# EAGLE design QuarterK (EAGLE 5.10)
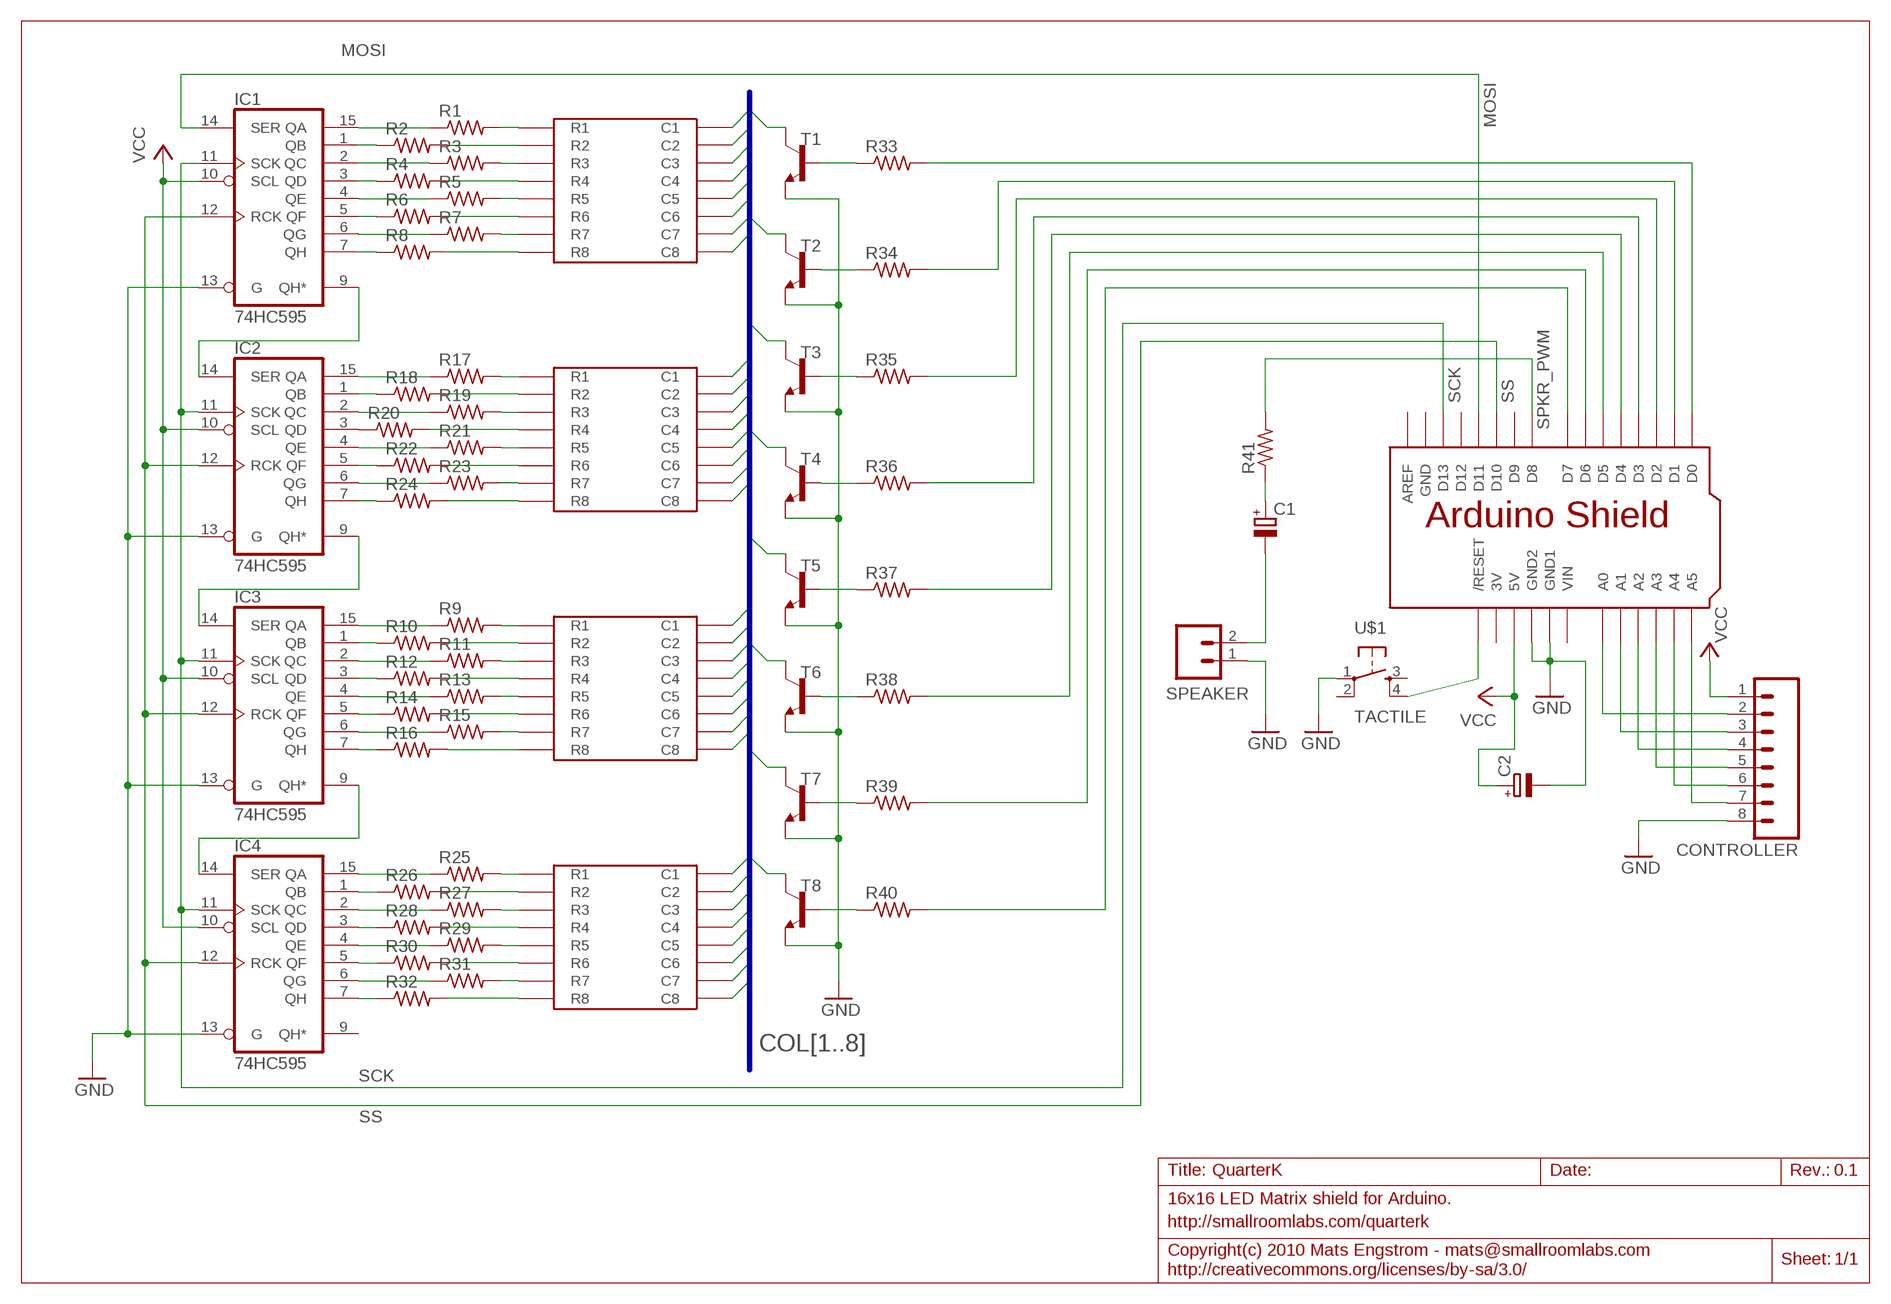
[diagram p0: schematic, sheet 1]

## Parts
C1  CPOL-EUE2.5-5  [E2,5-5]
C2  CPOL-EUE2.5-5  [E2,5-5]
CONTROLLER  M08  [1X08]
DISP1  LE-MM101STD  [LEDMATRIX-20MM-A]
DISP2  LE-MM101STD  [LEDMATRIX-20MM-A]
DISP3  LE-MM101STD  [LEDMATRIX-20MM-A]
DISP4  LE-MM101STD  [LEDMATRIX-20MM-A]
IC1  74HC595  74LS595N  [DIL16]
IC2  74HC595  74LS595N  [DIL16]
IC3  74HC595  74LS595N  [DIL16]
IC4  74HC595  74LS595N  [DIL16]
R1  R-US_0207/2V  [0207/2V]
R2  R-US_0207/2V  [0207/2V]
R3  R-US_0207/2V  [0207/2V]
R4  R-US_0207/2V  [0207/2V]
R5  R-US_0207/2V  [0207/2V]
R6  R-US_0207/2V  [0207/2V]
R7  R-US_0207/2V  [0207/2V]
R8  R-US_0207/2V  [0207/2V]
R9  R-US_0207/2V  [0207/2V]
R10  R-US_0207/2V  [0207/2V]
R11  R-US_0207/2V  [0207/2V]
R12  R-US_0207/2V  [0207/2V]
R13  R-US_0207/2V  [0207/2V]
R14  R-US_0207/2V  [0207/2V]
R15  R-US_0207/2V  [0207/2V]
R16  R-US_0207/2V  [0207/2V]
R17  R-US_0207/2V  [0207/2V]
R18  R-US_0207/2V  [0207/2V]
R19  R-US_0207/2V  [0207/2V]
R20  R-US_0207/2V  [0207/2V]
R21  R-US_0207/2V  [0207/2V]
R22  R-US_0207/2V  [0207/2V]
R23  R-US_0207/2V  [0207/2V]
R24  R-US_0207/2V  [0207/2V]
R25  R-US_0207/2V  [0207/2V]
R26  R-US_0207/2V  [0207/2V]
R27  R-US_0207/2V  [0207/2V]
R28  R-US_0207/2V  [0207/2V]
R29  R-US_0207/2V  [0207/2V]
R30  R-US_0207/2V  [0207/2V]
R31  R-US_0207/2V  [0207/2V]
R32  R-US_0207/2V  [0207/2V]
R33  R-US_0207/2V  [0207/2V]
R34  R-US_0207/2V  [0207/2V]
R35  R-US_0207/2V  [0207/2V]
R36  R-US_0207/2V  [0207/2V]
R37  R-US_0207/2V  [0207/2V]
R38  R-US_0207/2V  [0207/2V]
R39  R-US_0207/2V  [0207/2V]
R40  R-US_0207/2V  [0207/2V]
R41  R-US_0207/2V  [0207/2V]
SPEAKER  M02PTH  [1X02]
T1  2N2222  [TO92-EBC-OVAL]
T2  2N2222  [TO92-EBC-OVAL]
T3  2N2222  [TO92-EBC-OVAL]
T4  2N2222  [TO92-EBC-OVAL]
T5  2N2222  [TO92-EBC-OVAL]
T6  2N2222  [TO92-EBC-OVAL]
T7  2N2222  [TO92-EBC-OVAL]
T8  2N2222  [TO92-EBC-OVAL]
U$1  TACTILE  [TACTILE-PTH]
U$5  ARDUINO  [SHIELD-NOLEGEND]

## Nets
COL1: DISP1.PIN13(C1) DISP2.PIN13(C1) DISP3.PIN13(C1) DISP4.PIN13(C1) T1.C
COL2: DISP1.PIN3(C2) DISP2.PIN3(C2) DISP3.PIN3(C2) DISP4.PIN3(C2) T2.C
COL3: DISP1.PIN4(C3) DISP2.PIN4(C3) DISP3.PIN4(C3) DISP4.PIN4(C3) T3.C
COL4: DISP1.PIN10(C4) DISP2.PIN10(C4) DISP3.PIN10(C4) DISP4.PIN10(C4) T4.C
COL5: DISP1.PIN6(C5) DISP2.PIN6(C5) DISP3.PIN6(C5) DISP4.PIN6(C5) T5.C
COL6: DISP1.PIN11(C6) DISP2.PIN11(C6) DISP3.PIN11(C6) DISP4.PIN11(C6) T6.C
COL7: DISP1.PIN15(C7) DISP2.PIN15(C7) DISP3.PIN15(C7) DISP4.PIN15(C7) T7.C
COL8: DISP1.PIN16(C8) DISP2.PIN16(C8) DISP3.PIN16(C8) DISP4.PIN16(C8) T8.C
D0: R33.2 U$5.D0
D1: R34.2 U$5.D1
D2: R35.2 U$5.D2
D3: R36.2 U$5.D3
D4: R37.2 U$5.D4
D5: R38.2 U$5.D5
D6: R39.2 U$5.D6
D7: R40.2 U$5.D7
GND [power]: C2.- CONTROLLER.8 IC1.13(G) IC2.13(G) IC3.13(G) IC4.13(G) SPEAKER.1 T1.E T2.E T3.E T4.E T5.E T6.E T7.E T8.E U$1.1 U$5.GND1 U$5.GND2
MOSI: IC1.14(SER) U$5.D11
N$1: DISP4.PIN9(R1) R25.2
N$2: DISP4.PIN14(R2) R26.2
N$3: DISP4.PIN8(R3) R27.2
N$4: DISP4.PIN12(R4) R28.2
N$5: DISP4.PIN1(R5) R29.2
N$6: DISP4.PIN7(R6) R30.2
N$7: DISP4.PIN2(R7) R31.2
N$8: DISP4.PIN5(R8) R32.2
N$9: IC4.15(QA) R25.1
N$10: IC4.1(QB) R26.1
N$11: IC4.2(QC) R27.1
N$12: IC4.3(QD) R28.1
N$13: IC4.4(QE) R29.1
N$14: IC4.5(QF) R30.1
N$15: IC4.6(QG) R31.1
N$16: IC4.7(QH) R32.1
N$17: IC3.15(QA) R9.1
N$18: IC3.1(QB) R10.1
N$19: IC3.2(QC) R11.1
N$20: IC3.3(QD) R12.1
N$21: IC3.4(QE) R13.1
N$22: IC3.5(QF) R14.1
N$23: IC3.6(QG) R15.1
N$24: IC3.7(QH) R16.1
N$25: DISP3.PIN5(R8) R16.2
N$26: DISP3.PIN2(R7) R15.2
N$27: DISP3.PIN7(R6) R14.2
N$28: DISP3.PIN1(R5) R13.2
N$29: DISP3.PIN12(R4) R12.2
N$30: DISP3.PIN8(R3) R11.2
N$31: DISP3.PIN14(R2) R10.2
N$32: DISP3.PIN9(R1) R9.2
N$33: IC2.15(QA) R17.1
N$34: DISP2.PIN9(R1) R17.2
N$35: DISP2.PIN14(R2) R18.2
N$36: IC2.1(QB) R18.1
N$37: IC2.2(QC) R19.1
N$38: DISP2.PIN8(R3) R19.2
N$39: DISP2.PIN12(R4) R20.2
N$40: IC2.3(QD) R20.1
N$41: IC2.4(QE) R21.1
N$42: DISP2.PIN1(R5) R21.2
N$43: DISP2.PIN7(R6) R22.2
N$44: IC2.5(QF) R22.1
N$45: IC2.6(QG) R23.1
N$46: DISP2.PIN2(R7) R23.2
N$47: DISP2.PIN5(R8) R24.2
N$48: IC2.7(QH) R24.1
N$49: IC1.15(QA) R1.1
N$50: DISP1.PIN14(R2) R2.2
N$51: DISP1.PIN9(R1) R1.2
N$52: DISP1.PIN8(R3) R3.2
N$53: DISP1.PIN12(R4) R4.2
N$54: IC1.2(QC) R3.1
N$55: IC1.1(QB) R2.1
N$56: IC1.3(QD) R4.1
N$57: IC1.4(QE) R5.1
N$58: IC1.5(QF) R6.1
N$59: IC1.6(QG) R7.1
N$60: IC1.7(QH) R8.1
N$61: DISP1.PIN2(R7) R7.2
N$62: DISP1.PIN7(R6) R6.2
N$63: DISP1.PIN1(R5) R5.2
N$64: DISP1.PIN5(R8) R8.2
N$65: IC1.9(QH*) IC2.14(SER)
N$66: IC2.9(QH*) IC3.14(SER)
N$67: IC3.9(QH*) IC4.14(SER)
N$68: R40.1 T8.B
N$69: R39.1 T7.B
N$70: R38.1 T6.B
N$71: R37.1 T5.B
N$72: R36.1 T4.B
N$73: R35.1 T3.B
N$74: R34.1 T2.B
N$75: R33.1 T1.B
N$76: U$1.4 U$5.RESET(/RESET)
N$77: CONTROLLER.2 U$5.A0
N$78: CONTROLLER.3 U$5.A1
N$79: CONTROLLER.4 U$5.A2
N$80: CONTROLLER.5 U$5.A3
N$81: CONTROLLER.6 U$5.A4
N$82: CONTROLLER.7 U$5.A5
N$83: C1.- SPEAKER.2
N$84: C1.+ R41.1
SCK: IC1.11(SCK) IC2.11(SCK) IC3.11(SCK) IC4.11(SCK) U$5.D13
SPKR_PWM: R41.2 U$5.D8
SS: IC1.12(RCK) IC2.12(RCK) IC3.12(RCK) IC4.12(RCK) U$5.D10
VCC [power]: C2.+ CONTROLLER.1 IC1.10(SCL) IC2.10(SCL) IC3.10(SCL) IC4.10(SCL) U$5.5V
Unconnected: IC4.9(QH*) U$1.2 U$1.3 U$5.AREF U$5.D9 U$5.D12

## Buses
COL[1..8]

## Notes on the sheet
- 16x16 LED Matrix shield for Arduino.
- http://smallroomlabs.com/quarterk

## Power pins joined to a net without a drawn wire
3V: U$5.3V
GND: IC1.8(GND) IC2.8(GND) IC3.8(GND) IC4.8(GND) U$5.GND
VCC: IC1.16(VCC) IC2.16(VCC) IC3.16(VCC) IC4.16(VCC)
VIN: U$5.VIN

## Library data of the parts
C1 C2 = rcl:CPOL-EU: POLARIZED CAPACITOR, European symbol
CONTROLLER = SparkFun:M08: Header 8 Standard 8-pin 0.1" header. Use with straight break away headers (SKU : PRT-00116), right angle break away headers (PRT-00553), swiss pins (PRT-00743), machine pins (PRT-00117), and female headers (PRT-00115).
DISP1-DISP4 = SmallRoomLabs:LE-MM101: 20 mm LED Matrix 1.9mm LEDs 20x20mm package (Sure Electronics)
IC1-IC4 = 74xx-us:74*595: 8-bit SHIFT REGISTER, output latch
R1-R41 = rcl:R-US_: RESISTOR, American symbol
SPEAKER = SparkFun:M02: Header 2
T1-T8 = adafruit:2N2222: NPN TRANSISTOR Big oval pads
U$1 = SmallRoomLabs:TACTILE
U$5 = SmallRoomLabs:ARDUINO

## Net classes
0 default: width 0.305 mm, clearance 0.254 mm
1 power: width 0.508 mm, clearance 0.254 mm

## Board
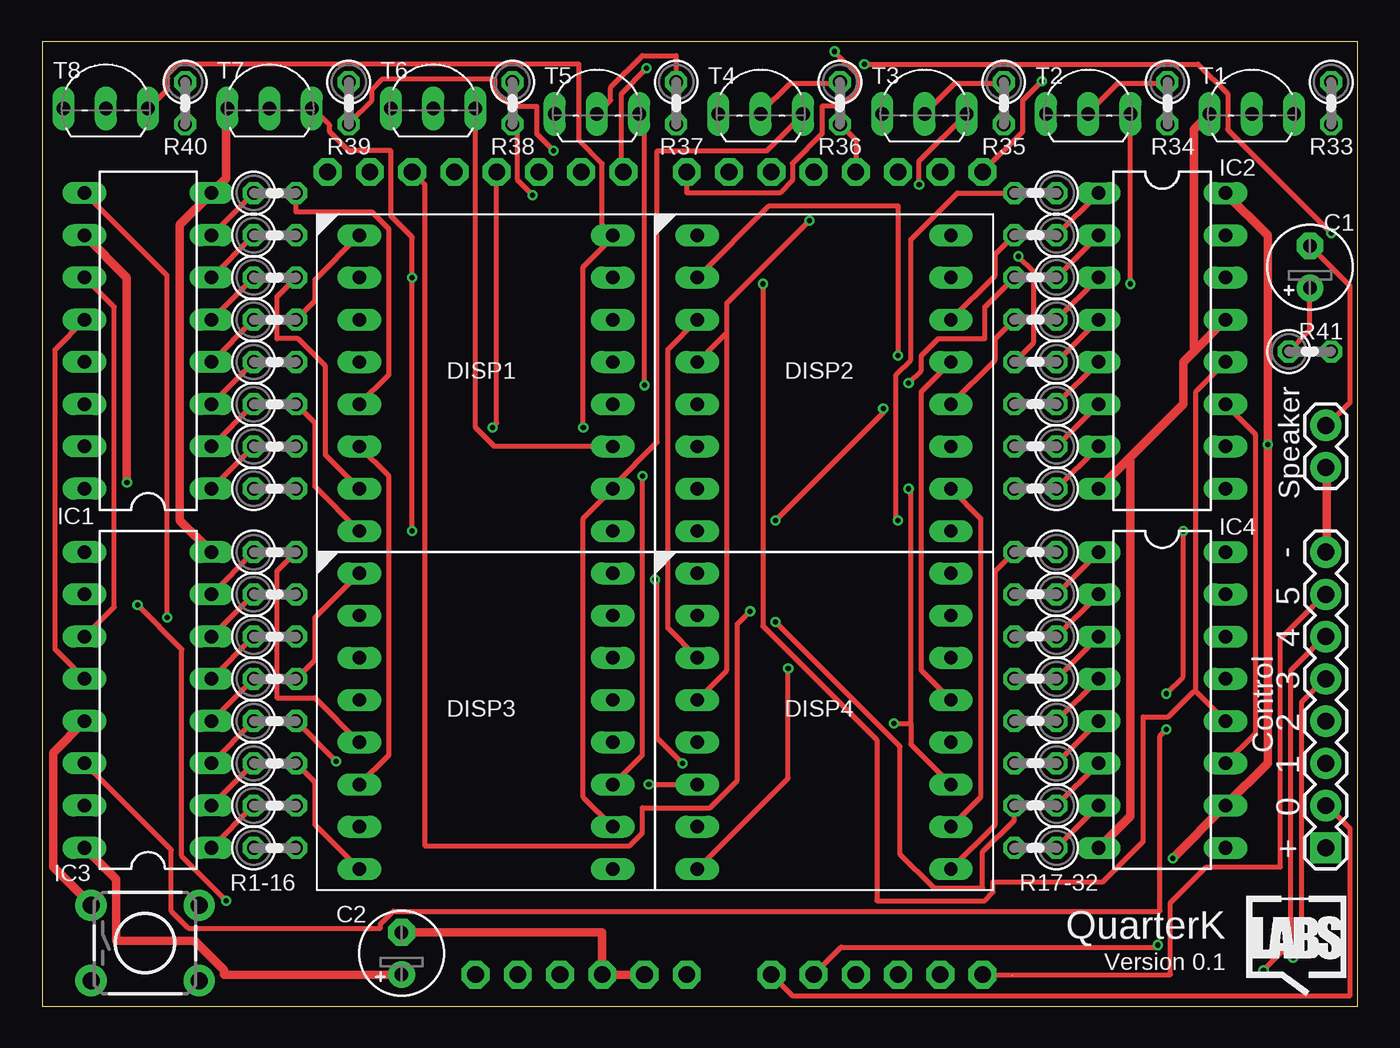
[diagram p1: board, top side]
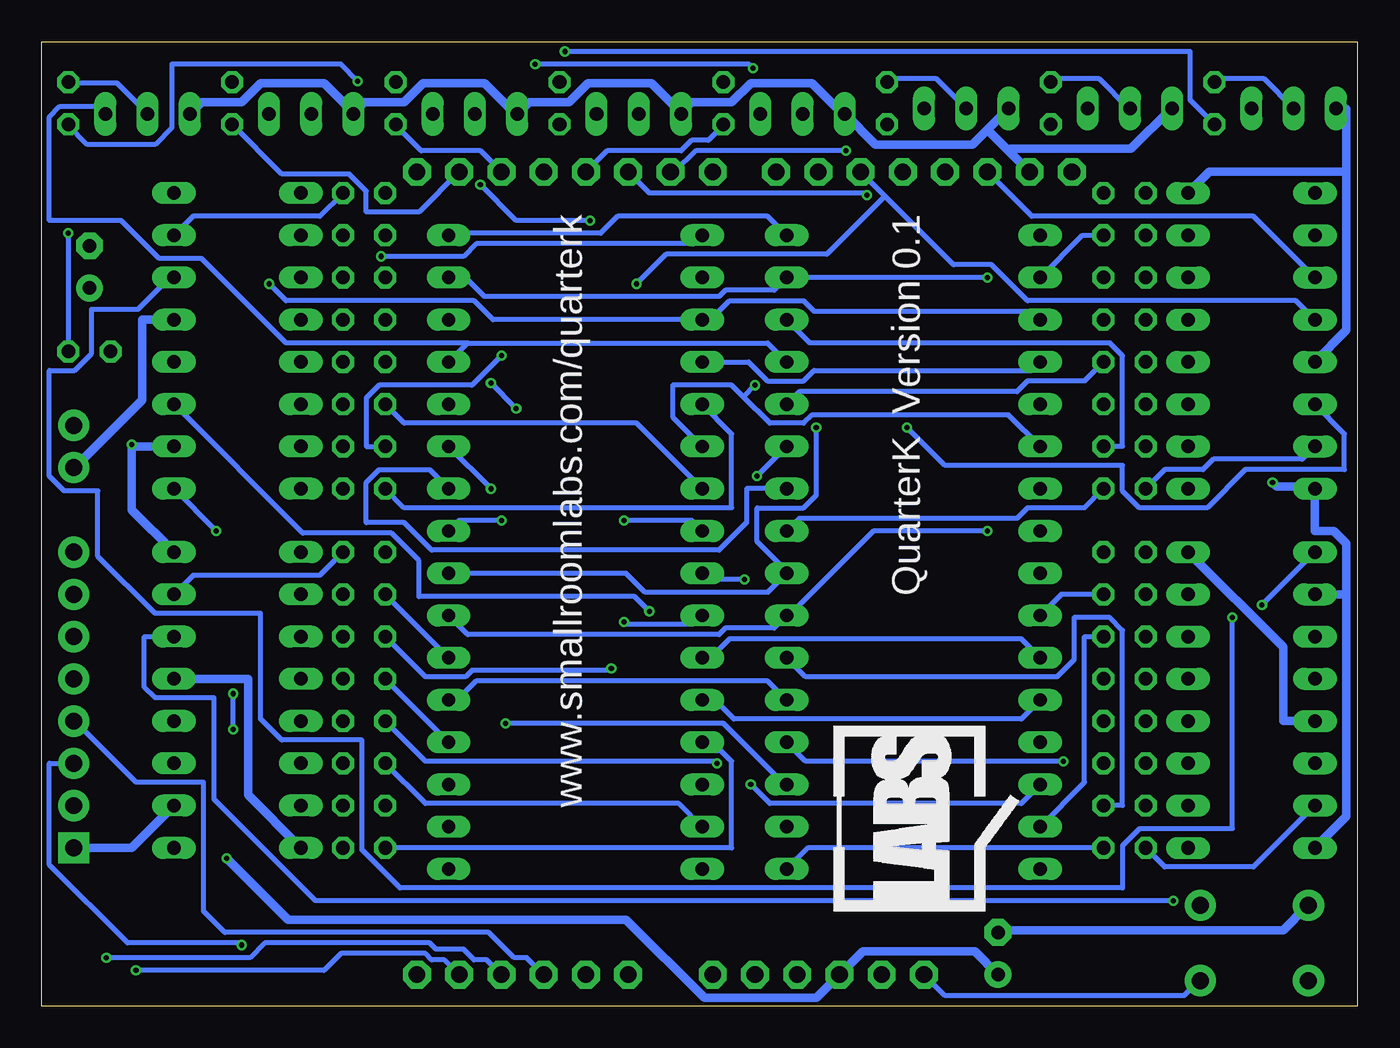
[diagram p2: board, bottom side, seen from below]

Size 79.08 x 58 mm. Coordinates in mm from the lower left corner, seen from the top.
Outline: 0,0 79.08,0 79.08,58 0,58 0,0
Copper layers (1*16): Top 0.035mm / dielectric 1.5mm / Bottom 0.035mm
Design rules "Fusion_eagle_rule_v1.1": minimum track width 6mil, minimum drill 12mil, track to track 6mil, track to pad 6mil, pad to pad 6mil, via to via 6mil, smd to smd 0mil, copper to edge 10mil, drill to drill 10mil, minimum pad ring 10mil, minimum via ring 6mil, stop-mask expansion 2mil, vias tented up to drill 100mil, thermal gap 10mil

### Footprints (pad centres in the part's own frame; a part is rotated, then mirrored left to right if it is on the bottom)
E2,5-5 = drill 0.813 pad 1.6 round: + -1.27,0 | drill 0.813 pad 1.6 octagon: - 1.27,0
1X08 = drill 1.016 pad 1.88 square: 1 0,0 | drill 1.016 pad 1.88 round: 2 2.54,0; 3 5.08,0; 4 7.62,0; 5 10.16,0; 6 12.7,0; 7 15.24,0; 8 17.78,0
LEDMATRIX-20MM-A = drill 0.8 long: PIN1 -7.62,-7.62; PIN2 -5.08,-7.62; PIN3 -2.54,-7.62; PIN4 0,-7.62; PIN5 2.54,-7.62; PIN6 5.08,-7.62; PIN7 7.62,-7.62; PIN8 10.16,-7.62; PIN9 10.16,7.62; PIN10 7.62,7.62; PIN11 5.08,7.62; PIN12 2.54,7.62; PIN13 0,7.62; PIN14 -2.54,7.62; PIN15 -5.08,7.62; PIN16 -7.62,7.62
DIL16 = drill 0.813 long: 1 -8.89,-3.81; 2 -6.35,-3.81; 3 -3.81,-3.81; 4 -1.27,-3.81; 5 1.27,-3.81; 6 3.81,-3.81; 7 6.35,-3.81; 8 8.89,-3.81; 9 8.89,3.81; 10 6.35,3.81; 11 3.81,3.81; 12 1.27,3.81; 13 -1.27,3.81; 14 -3.81,3.81; 15 -6.35,3.81; 16 -8.89,3.81
0207/2V = drill 0.813 octagon: 1 -1.27,0; 2 1.27,0
1X02 = drill 1.016 pad 1.88 round: 1 0,0; 2 2.54,0
TO92-EBC-OVAL = drill 0.813 long: B 0,-1.27; C 2.54,-1.27; E -2.54,-1.27
TACTILE-PTH = drill 1.016 pad 1.88 round: 1 -3.251,2.261; 2 3.251,2.261; 3 -3.251,-2.261; 4 3.251,-2.261
SHIELD-NOLEGEND = drill 1 pad 1.676 octagon: 3V -8.89,-24.13; 5V -6.35,-24.13; A0 6.35,-24.13; A1 8.89,-24.13; A2 11.43,-24.13; A3 13.97,-24.13; A4 16.51,-24.13; A5 19.05,-24.13; AREF -20.32,24.13; D0 19.05,24.13; D1 16.51,24.13; D2 13.97,24.13; D3 11.43,24.13; D4 8.89,24.13; D5 6.35,24.13; D6 3.81,24.13; D7 1.27,24.13; D8 -2.54,24.13; D9 -5.08,24.13; D10 -7.62,24.13; D11 -10.16,24.13; D12 -12.7,24.13; D13 -15.24,24.13; GND -17.78,24.13; GND1 -1.27,-24.13; GND2 -3.81,-24.13; RESET -11.43,-24.13; VIN 1.27,-24.13

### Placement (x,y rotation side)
C1  76.2,44.45 90 top
C2  21.59,3.17 90 top
CONTROLLER  77.15,9.53 90 top
DISP1  26.67,38.73 270 top
DISP2  46.99,38.73 270 top
DISP3  26.67,18.41 270 top
DISP4  46.99,18.41 270 top
IC1  6.35,40.01 90 top
IC2  67.31,40.01 270 top
IC3  6.35,18.41 90 top
IC4  67.31,18.41 270 top
R1  13.97,31.11 0 top
R2  13.97,33.66 0 top
R3  13.97,36.2 0 top
R4  13.97,38.73 0 top
R5  13.97,41.27 0 top
R6  13.97,43.81 0 top
R7  13.97,46.35 0 top
R8  13.97,48.9 0 top
R9  13.97,9.53 0 top
R10  13.97,12.06 0 top
R11  13.97,14.61 0 top
R12  13.97,17.14 0 top
R13  13.97,19.68 0 top
R14  13.97,22.23 0 top
R15  13.97,24.77 0 top
R16  13.97,27.3 0 top
R17  59.69,48.9 180 top
R18  59.69,46.35 180 top
R19  59.69,43.81 180 top
R20  59.69,41.27 180 top
R21  59.69,38.73 180 top
R22  59.69,36.2 180 top
R23  59.69,33.66 180 top
R24  59.69,31.11 180 top
R25  59.69,27.3 180 top
R26  59.69,24.77 180 top
R27  59.69,22.23 180 top
R28  59.69,19.68 180 top
R29  59.69,17.14 180 top
R30  59.69,14.61 180 top
R31  59.69,12.06 180 top
R32  59.69,9.53 180 top
R33  77.47,54.29 270 top
R34  67.63,54.29 270 top
R35  57.78,54.29 270 top
R36  47.94,54.29 270 top
R37  38.1,54.29 270 top
R38  28.26,54.29 270 top
R39  18.41,54.29 270 top
R40  8.57,54.29 270 top
R41  76.2,39.37 0 top
SPEAKER  77.15,32.38 90 top
T1  72.71,54.93 0 top
T2  62.87,54.93 0 top
T3  53.02,54.93 0 top
T4  43.18,54.93 0 top
T5  33.34,54.93 0 top
T6  23.5,55.24 0 top
T7  13.65,55.24 0 top
T8  3.81,55.24 0 top
U$1  6.17,3.81 0 top
U$2  [SRL-LOGO-SILK-10MM]  20.32,5.71 90 bottom
U$3  [SEL-LOGO-SILK-5MM]  72.39,0.64 0 top
U$5  37.47,26.04 0 top

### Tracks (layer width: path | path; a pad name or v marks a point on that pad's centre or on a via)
COL1
  Top 0.305: DISP4.PIN13 52.83,20.19 52.83,36.96 DISP2.PIN13
  Bottom 0.305: DISP3.PIN13 35.43,19.56 52.96,19.56 54.1,18.41 DISP4.PIN13 | DISP1.PIN13 35.43,39.88 53.47,39.88 | DISP2.PIN13 53.47,39.88 | T1.C 75.69,54.1 77.98,54.1 78.61,53.47 78.61,47.24 74.3,47.24 72.01,44.96 69.47,44.96 64.39,39.88 53.47,39.88
COL2  (via drill 0.3)
  Top 0.305: v65.41,43.43 T2.C | DISP4.PIN3 37.59,22.73 37.59,39.5 DISP2.PIN3
  Bottom 0.305: DISP3.PIN3 20.19,22.1 37.72,22.1 38.86,20.95 DISP4.PIN3 | DISP1.PIN3 19.56,41.78 32.64,41.78 33.27,42.42 37.72,42.42 38.86,41.27 DISP2.PIN3 51.94,41.27 53.09,42.42 64.39,42.42 v65.41,43.43
COL3  (via drill 0.3)
  Top 0.305: v52.7,49.4 52.7,50.8 T3.C | v46.1,47.24 41.15,42.29 41.15,40.51 | 41.15,40.51 DISP2.PIN4 | DISP4.PIN4 41.15,20.19 41.15,40.51
  Bottom 0.305: DISP3.PIN4 20.19,17.27 37.47,17.27 38.61,18.41 DISP4.PIN4 | DISP1.PIN4 19.56,38.23 32.64,38.23 33.27,37.59 35.43,37.59 36.58,38.73 DISP2.PIN4 | v52.7,49.4 50.55,47.24 v46.1,47.24
COL4
  Top 0.305: DISP4.PIN10 56.39,12.57 56.39,29.34 DISP2.PIN10 | DISP3.PIN10 32.51,12.57 32.51,29.34 DISP1.PIN10 34.29,31.24 36.96,33.91 36.96,51.44 43.56,51.44 45.72,53.59 T4.C
  Bottom 0.305: DISP2.PIN10 55.75,32.26 58.8,32.26 59.56,31.5 59.56,29.08 57.28,29.08 55.63,27.43 38.35,27.43 36.7,29.08 36.7,31.11 DISP1.PIN10
COL5  (via drill 0.3)
  Top 0.305: DISP3.PIN6 20.83,15.11 20.83,31.88 DISP1.PIN6 | v36.45,13.34 DISP4.PIN6 | v36.2,37.34 36.2,53.34 T5.C
  Bottom 0.305: v36.45,13.34 35.31,12.19 20.19,12.19 DISP3.PIN6 | DISP2.PIN6 41.15,35.43 41.15,37.34 37.59,37.34 36.89,36.64 | 36.89,36.64 35.31,35.05 33.27,35.05 32.77,35.56 20.95,35.56 DISP1.PIN6 | 36.89,36.64 v36.2,37.34
COL6  (via drill 0.3)
  Top 0.305: DISP4.PIN11 52.2,15.75 52.2,17.02 | 52.2,17.02 52.2,30.99 v52.07,31.11 | DISP3.PIN11 36.07,15.11 v36.07,31.88 | T6.C 26.04,34.8 27.18,33.66 DISP1.PIN11 | v51.18,17.02 52.2,17.02
  Bottom 0.305: v52.07,31.11 DISP2.PIN11 | v36.07,31.88 DISP1.PIN11 | v51.18,17.02 38.1,17.02 34.42,13.34 DISP3.PIN11
COL7  (via drill 0.3)
  Top 0.305: T7.C 16.26,53.98 17.27,52.96 17.27,52.58 18.41,51.44 20.95,51.44 20.95,47.5 22.23,46.23 v22.23,43.81 v22.23,28.57
  Bottom 0.305: DISP4.PIN15 53.47,22.35 38.35,22.35 37.97,22.73 35.05,22.73 DISP3.PIN15 34.16,23.5 29.08,28.57 v22.23,28.57 | DISP2.PIN15 53.59,43.81 52.45,42.67 38.35,42.67 37.97,43.05 35.05,43.05 DISP1.PIN15 v22.23,43.81
COL8  (via drill 0.3)
  Top 0.305: T8.C 7.49,55.12 7.49,56.01 8.13,56.64 32.26,56.64 32.26,52.07 33.66,50.67 33.66,46.99 DISP1.PIN16 34.29,46.23 32.51,44.45 v32.51,34.8
  Bottom 0.305: DISP4.PIN16 43.94,26.04 42.8,24.89 35.43,24.89 DISP3.PIN16 34.29,26.16 36.07,27.94 36.07,29.97 33.27,29.97 32.51,30.73 v32.51,34.8 | DISP1.PIN16 35.43,47.5 44.45,47.5 45.47,46.48 54.48,46.48 DISP2.PIN16
D0  (via drill 0.3)
  Top 0.305: v60.07,55.63 58.93,54.48 58.93,52.58 U$5.D0
  Bottom 0.305: v60.07,55.63 61.09,56.64 71.25,56.64 71.25,52.83 72.26,51.82 76.33,51.82 77.47,52.96 R33.2
D1
  Bottom 0.305: U$5.D1 56.39,47.75 59.56,47.75 59.56,49.02 60.58,50.04 64.64,50.04 R34.2
D2
  Bottom 0.305: U$5.D2 52.7,51.44 56.26,51.44 57.78,52.96 R35.2
D3
  Top 0.305: U$5.D3 48.9,52.07 R36.2
D4
  Bottom 0.305: U$5.D4 45.09,51.44 40.64,51.44 40.01,52.07 38.99,52.07 38.1,52.96 R37.2
D5  (via drill 0.3)
  Top 0.305: v29.46,48.77 28.57,49.66 28.57,52.7 R38.2
  Bottom 0.305: v29.46,48.77 29.59,48.9 42.55,48.9 U$5.D5
D6  (via drill 0.3)
  Top 0.305: v30.73,51.44 29.72,52.45 29.72,54.1 28.19,54.1 27.18,55.12 27.18,55.75 20.45,55.75 19.81,55.12 19.81,54.48 18.41,53.09 R39.2
  Bottom 0.305: v30.73,51.44 39.75,51.44 41.02,50.16 U$5.D6
D7  (via drill 0.3)
  Top 0.305: v47.62,57.4 49.02,56.01 49.02,55.12 48.01,54.1 46.86,54.1 46.86,52.45 45.09,50.67 45.09,49.66 44.32,48.9 38.73,48.9 U$5.D7
  Bottom 0.305: v47.62,57.4 10.03,57.4 10.03,54.48 R40.2
GND
  Top 0.508: C2.- 33.66,4.45 U$5.GND2 U$5.GND1 | IC3.13 0.64,15.24 0.64,8.38 2.92,6.1 U$1.1 | CONTROLLER.8 77.22,27.3 77.22,32.38 SPEAKER.1 | 65.28,32.89 68.58,36.2 68.58,38.73 69.34,39.5 | 65.28,32.89 IC2.8 | 69.34,39.5 IC2.13 | T1.E 69.22,52.7 69.22,39.62 69.34,39.5 | IC4.8 65.41,11.43 65.41,32.77 65.28,32.89 | T7.E 11.05,53.98 11.05,49.78 IC1.8 8.26,46.99 8.26,29.21 IC3.8
  Bottom 0.508: IC3.8 4.45,21.59 4.45,17.14 IC3.13 | C2.- 21.46,4.57 4.45,4.57 3.05,5.97 U$1.1 | IC4.8 66.67,12.7 66.67,19.68 IC4.13 | IC2.13 73.03,41.27 73.03,36.45 77.09,32.38 SPEAKER.1 | IC1.13 0.64,40.64 0.64,50.16 | 0.64,50.16 0.64,53.98 T8.E | IC1.8 8.89,50.16 0.64,50.16 | 22.23,52.7 T6.E | 22.23,52.7 23.11,51.82 28.96,51.82 T5.E 30.99,53.72 32.77,55.5 36.45,55.5 37.59,54.36 40.01,54.36 40.64,53.72 T4.E 40.77,53.85 42.42,55.5 46.23,55.5 47.37,54.36 49.78,54.36 T3.E 50.67,53.72 52.45,55.5 56.13,55.5 57.28,54.36 59.69,54.36 60.33,53.72 T2.E 60.45,53.85 62.1,55.5 65.91,55.5 67.06,54.36 69.47,54.36 T1.E | 20.95,51.44 U$5.GND | 20.95,51.44 22.23,52.7 | T7.E 11.18,53.98 13.59,51.56 20.83,51.56 20.95,51.44
MOSI  (via drill 0.3)
  Top 0.305: v27.05,34.8 27.3,35.05 U$5.D11
  Bottom 0.305: IC1.14 0.76,34.42 0.76,32.26 6.73,32.26 9.02,29.97 13.08,29.97 14.1,30.99 14.1,32.51 24.77,32.51 v27.05,34.8
N$1
  Top 0.305: DISP4.PIN9 57.28,10.92 57.28,26.16 R25.2
N$2
  Bottom 0.305: DISP4.PIN14 R26.2
N$3  (via drill 0.3)
  Top 0.305: DISP4.PIN8 44.83,13.72 v44.83,20.32
  Bottom 0.305: v44.83,20.32 44.96,20.19 53.21,20.19 53.59,19.81 56.01,19.81 R27.2
N$4
  Bottom 0.305: DISP4.PIN12 R28.2
N$5  (via drill 0.3)
  Top 0.305: v36.83,25.65 36.96,25.53 36.96,16.13 v38.48,14.61
  Bottom 0.305: DISP4.PIN1 38.99,25.65 v36.83,25.65 | v38.48,14.61 38.61,14.73 56.01,14.73 R29.2
N$6
  Bottom 0.305: DISP4.PIN7 40.77,12.19 56.01,12.19 R30.2
N$7  (via drill 0.3)
  Top 0.305: v44.07,23.11 51.56,15.62 51.56,9.14 53.59,7.11 56.52,7.11 56.52,9.27 58.42,11.18 R31.2
  Bottom 0.305: DISP4.PIN2 39.88,22.99 43.94,22.99 v44.07,23.11
N$8
  Bottom 0.305: DISP4.PIN5 38.86,15.37 38.23,15.37 37.59,14.73 37.59,9.53 R32.2
N$9
  Bottom 0.305: R25.1 62.36,25.91 69.98,25.91 IC4.15
N$10
  Top 0.305: R26.1 IC4.1
N$11
  Top 0.305: R27.1 IC4.2
N$12
  Top 0.305: R28.1 IC4.3
N$13
  Top 0.305: R29.1 IC4.4
N$14
  Top 0.305: R30.1 IC4.5
N$15
  Top 0.305: R31.1 IC4.6
N$16
  Top 0.305: R32.1 IC4.7
N$17
  Bottom 0.305: IC3.15 6.22,8.38 11.56,8.38 R9.1
N$18
  Top 0.305: IC3.1 R10.1
N$19
  Top 0.305: IC3.2 R11.1
N$20
  Top 0.305: IC3.3 R12.1
N$21
  Top 0.305: IC3.4 R13.1
N$22
  Top 0.305: IC3.5 R14.1
N$23
  Top 0.305: IC3.6 R15.1
N$24
  Top 0.305: IC3.7 R16.1
N$25
  Top 0.305: DISP3.PIN5 16.38,18.54 14.1,18.54 14.1,26.16 R16.2
N$26
  Bottom 0.305: DISP3.PIN2 17.78,24.77 R15.2
N$27
  Bottom 0.305: DISP3.PIN7 16.38,13.46 16.38,22.23 R14.2
N$28
  Top 0.305: DISP3.PIN1 16.38,23.37 16.38,20.83 R13.2
N$29  (via drill 0.3)
  Top 0.305: v17.65,14.73 R12.2
  Bottom 0.305: DISP3.PIN12 33.15,14.73 v17.65,14.73
N$30
  Top 0.305: DISP3.PIN8 16.38,10.92 16.38,13.46 R11.2
N$31
  Bottom 0.305: DISP3.PIN14 33.15,19.81 18.03,19.81 17.02,20.83 17.02,23.37 14.86,23.37 14.1,22.61 14.1,12.06 R10.2
N$32
  Bottom 0.305: DISP3.PIN9 33.02,9.53 R9.2
N$33
  Bottom 0.305: R17.1 62.36,47.5 69.98,47.5 IC2.15
N$34  (via drill 0.3)
  Top 0.305: v51.44,29.21 51.31,29.34 51.31,37.97 52.2,38.86 52.2,46.1 54.99,48.9 R17.2
  Bottom 0.305: DISP2.PIN9 53.98,29.21 v51.44,29.21
N$35
  Top 0.305: DISP2.PIN14 57.28,43.94 57.28,45.21 R18.2
N$36
  Top 0.305: R18.1 IC2.1
N$37
  Top 0.305: R19.1 IC2.2
N$38  (via drill 0.3)
  Top 0.305: v44.07,29.21 50.55,35.69 v50.55,35.94 | v52.07,37.47 52.83,38.23 52.83,39.12 53.85,40.13 56.64,40.13 56.64,42.04 R19.2
  Bottom 0.305: DISP2.PIN8 40.01,29.21 v44.07,29.21 | v50.55,35.94 v52.07,37.47
N$39
  Top 0.305: DISP2.PIN12 57.28,38.86 57.28,40.13 R20.2
N$40
  Top 0.305: R20.1 IC2.3
N$41
  Top 0.305: R21.1 IC2.4
N$42  (via drill 0.3)
  Top 0.305: v58.67,45.09 59.56,44.2 59.56,39.88 R21.2
  Bottom 0.305: DISP2.PIN1 39.88,45.85 52.96,45.85 53.72,45.09 v58.67,45.09
N$43
  Bottom 0.305: DISP2.PIN7 43.31,35.05 57.28,35.05 R22.2
N$44
  Top 0.305: R22.1 IC2.5
N$45
  Top 0.305: R23.1 IC2.6
N$46  (via drill 0.3)
  Top 0.305: DISP2.PIN2 43.69,48.13 51.44,48.13 v51.44,39.12
  Bottom 0.305: v51.44,39.12 53.21,37.34 58.8,37.34 59.56,36.58 59.56,33.66 R23.2
N$47
  Bottom 0.305: DISP2.PIN5 37.59,34.42 37.59,29.97 57.28,29.97 R24.2
N$48
  Top 0.305: R24.1 IC2.7
N$49
  Bottom 0.305: IC1.15 3.3,32.89 8.64,32.89 9.27,32.26 11.56,32.26 R1.1
N$50
  Bottom 0.305: DISP1.PIN14 32.89,39.88 14.86,39.88 14.1,39.12 14.1,33.66 R2.2
N$51
  Bottom 0.305: DISP1.PIN9 33.53,29.34 20.45,29.34 19.81,29.97 16.38,29.97 R1.2
N$52
  Top 0.305: DISP1.PIN8 16.38,31.24 16.38,35.05 R3.2
N$53
  Bottom 0.305: DISP1.PIN12 33.53,36.96 20.45,36.96 19.81,37.59 16.38,37.59 R4.2
N$54
  Top 0.305: IC1.2 R3.1
N$55
  Top 0.305: IC1.1 R2.1
N$56
  Top 0.305: IC1.3 R4.1
N$57
  Top 0.305: IC1.4 R5.1
N$58
  Top 0.305: IC1.5 R6.1
N$59
  Top 0.305: IC1.6 R7.1
N$60
  Top 0.305: IC1.7 R8.1
N$61
  Bottom 0.305: DISP1.PIN2 16.51,46.35 R7.2
N$62
  Top 0.305: DISP1.PIN7 17.02,33.15 17.02,38.48 15.37,40.13 14.1,40.13 14.1,42.67 R6.2
N$63
  Top 0.305: DISP1.PIN1 16.38,43.69 16.38,42.42 R5.2
N$64
  Top 0.305: DISP1.PIN5 20.83,37.97 20.83,46.74 19.81,47.75 15.24,47.75 R8.2
N$65  (via drill 0.3)
  Top 0.305: IC1.9 7.49,43.94 v7.49,23.37
  Bottom 0.305: v7.49,23.37 7.49,10.67 13.08,10.67 14.1,9.65 14.1,7.11 57.53,7.11 59.82,9.4 59.82,16 64.64,16 65.91,17.27 65.91,23.62 72.26,23.62 75.69,27.05 75.69,30.99 77.72,30.99 78.61,31.88 78.61,38.23 77.09,38.23 76.07,39.24 76.07,41.91 73.28,41.91 71.37,43.81 IC2.14
N$66  (via drill 0.3)
  Top 0.305: IC3.14 7.75,9.4 7.75,5.71 8.76,4.7 20.32,4.7 20.32,4.95 21.08,5.71 67.18,5.71 67.18,16.26 v67.56,16.64 | v67.56,18.8 68.58,19.81 v68.58,28.57
  Bottom 0.305: v67.56,16.64 v67.56,18.8 | v68.58,28.57 IC2.9
N$67  (via drill 0.3)
  Top 0.305: v5.71,24.13 8.38,21.46 8.38,9.02 v11.05,6.35
  Bottom 0.305: v5.71,24.13 IC3.9 | v11.05,6.35 62.61,6.35 68.71,12.45 68.71,18.54 72.26,18.54 72.9,19.18 72.9,22.23 IC4.14
N$68
  Bottom 0.305: T8.B 5.59,55.75 8.38,55.75 R40.1
N$69
  Bottom 0.305: T7.B 13.72,53.98 15.49,55.75 18.29,55.75 18.41,55.63 R39.1
N$70
  Bottom 0.305: T6.B 25.27,55.75 28.07,55.75 R38.1
N$71
  Top 0.305: T5.B 34.16,54.48 34.16,55.24 36.07,57.15 38.1,57.15 R37.1
N$72
  Top 0.305: T4.B 43.18,53.72 44.96,55.5 47.88,55.5 R36.1
N$73
  Top 0.305: T3.B 54.86,55.5 57.78,55.5 R35.1
N$74
  Top 0.305: T2.B 62.87,53.72 64.64,55.5 67.56,55.5 R34.1
N$75
  Bottom 0.305: T1.B 74.55,55.5 77.47,55.5 R33.1
N$76
  Bottom 0.305: U$5.RESET 24.77,0.64 10.41,0.64 9.53,1.52 U$1.4
N$77
  Top 0.305: U$5.A0 45.09,0.64 78.61,0.64 78.61,10.67 77.22,12.06 CONTROLLER.2
N$78  (via drill 0.3)
  Top 0.305: U$5.A1 48.01,3.56 67.06,3.56 v67.06,3.68
  Bottom 0.305: v67.06,3.68 67.18,3.81 73.91,3.81 78.61,8.51 78.61,14.61 CONTROLLER.3
N$79
  Bottom 0.305: U$5.A2 49.91,2.92 50.67,2.92 52.2,4.45 68.07,4.45 69.34,5.71 69.34,13.46 73.41,13.46 77.09,17.14 CONTROLLER.4
N$80  (via drill 0.3)
  Top 0.305: v75.18,2.92 75.69,3.43 75.69,18.29 77.09,19.68 CONTROLLER.5
  Bottom 0.305: U$5.A3 52.32,2.79 53.09,2.79 53.72,3.43 55.37,3.43 55.75,3.81 65.66,3.81 66.55,2.92 v75.18,2.92
N$81  (via drill 0.3)
  Top 0.305: v73.41,2.16 75.06,3.81 75.06,20.19 77.09,22.23 CONTROLLER.6
  Bottom 0.305: U$5.A4 54.86,2.79 55.63,2.79 56.01,3.17 61.09,3.17 62.1,2.16 v73.41,2.16
N$82
  Top 0.305: U$5.A5 67.82,1.91 67.82,6.22 69.98,8.38 74.42,8.38 74.42,22.1 77.09,24.77 CONTROLLER.7
N$83
  Top 0.305: C1.- 78.61,43.31 78.61,36.32 77.22,34.92 SPEAKER.2
N$84
  Top 0.305: R41.1 76.2,40.64 C1.+
SCK  (via drill 0.3)
  Top 0.305: IC4.11 72.9,16.38 72.9,34.42 IC2.11 | IC3.11 4.32,24 4.32,42.04 IC1.11 | v42.55,23.75 41.78,22.99 41.78,13.59 40.13,11.94 36.07,11.94 36.07,10.41 35.31,9.65 22.99,9.65 22.99,49.4 U$5.D13
  Bottom 0.305: U$5.D13 19.56,47.5 6.22,47.5 IC1.11 | IC2.11 63.37,28.45 58.04,28.45 56.39,26.8 56.39,24.64 43.43,24.64 v42.55,23.75
SPKR_PWM  (via drill 0.3)
  Top 0.305: v77.47,46.48 71.25,52.7 71.25,54.86 69.47,56.64 v49.4,56.64 | v36.32,56.39 34.8,54.86 34.8,50.29 U$5.D8
  Bottom 0.305: v77.47,46.48 R41.2 | v49.4,56.64 36.58,56.64 v36.32,56.39
SS  (via drill 0.3)
  Top 0.305: 69.34,18.92 IC4.12 | 69.34,18.92 69.34,36.96 IC2.12 | IC3.12 0.76,21.46 0.76,39.5 IC1.12 | v43.31,43.43 43.31,22.86 50.16,16 50.16,6.35 56.64,6.35 57.15,6.86 57.15,7.49 63.75,7.49 66.17,9.91 66.17,17.4 67.69,17.4 69.22,18.92 69.34,18.92
  Bottom 0.305: 28.38,48.7 24.26,44.58 21.97,44.58 19.81,42.42 3.68,42.42 IC1.12 | 28.38,48.7 U$5.D10 | v43.31,43.43 41.53,45.21 31.88,45.21 28.38,48.7
VCC  (via drill 0.3)
  Top 0.508: IC2.16 73.66,46.35 v73.66,33.78 73.66,14.61 IC4.10 v67.94,8.89 | IC1.10 5.08,43.81 v5.08,31.5 | C2.+ 10.92,1.91 10.92,2.16 9.14,3.94 4.45,3.94 4.45,7.62 IC3.16
  Bottom 0.508: IC4.10 73.66,9.53 CONTROLLER.1 | IC4.16 73.66,29.84 73.66,33.66 | 73.66,33.66 IC2.10 | v73.66,33.78 73.66,33.66 | C2.+ 22.99,3.3 29.72,3.3 U$5.5V 32.51,0.51 39.24,0.51 43.94,5.21 64.26,5.21 v67.94,8.89 | IC3.16 0.64,11.43 0.64,24.77 | 0.64,24.77 IC3.10 | 0.64,24.77 0.64,27.81 1.4,28.57 2.54,28.57 IC1.16 2.67,31.24 4.83,31.24 v5.08,31.5

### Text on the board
tPlace: Speaker | - | 5 | 4 | 3 | 2 | Control | 1 | 0 | + | QuarterK | Version 0.1
bPlace: QuarterK Version 0.1 | www.smallroomlabs.com/quarterk
tNames: R1-16 | R17-32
